// Mitsubishi GX Works2 project: jk3uRS485-1   PLC: FX3U/FX3UC

PROGRAM MAIN
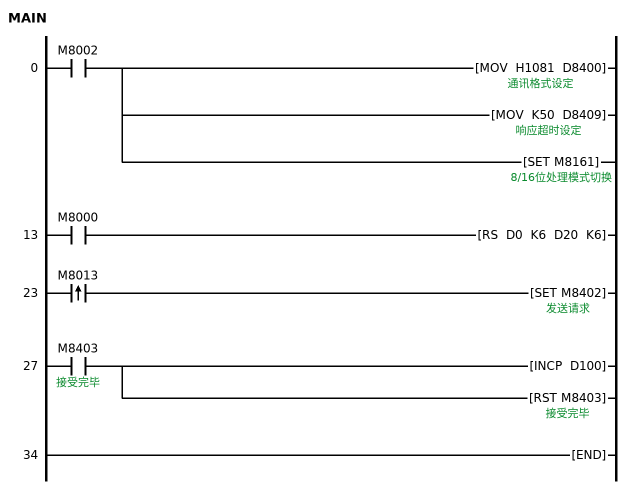
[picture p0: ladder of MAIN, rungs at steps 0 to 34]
0     LD      M8002
      MOV     H1081 D8400  ; 通讯格式设定
      MOV     K50 D8409  ; 响应超时设定
      SET     M8161  ; 8/16位处理模式切换
13    LD      M8000
      RS      D0 K6 D20 K6
23    LDP     M8013
      SET     M8402  ; 发送请求
27    LD      M8403  ; 接受完毕
      INCP    D100
      RST     M8403  ; 接受完毕
34    END
END_PROGRAM
